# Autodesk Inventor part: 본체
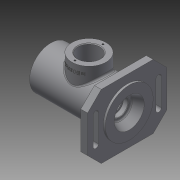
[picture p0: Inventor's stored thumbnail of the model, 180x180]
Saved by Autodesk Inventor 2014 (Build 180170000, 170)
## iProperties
Created: 2017-10
Part Number: 본체
Material: Generic
Document SubType Name: Modeling
Designer: geosung1
Density: 1 g/cm^3
Appearance: Default
Author: geosung1
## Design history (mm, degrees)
sketch "스케치1"
  geometry: L1 (-57.5, 0)-(57.5, 0); L2 (-57.5, 0)-(-57.5, 31); L3 (-57.5, 31)-(54.5, 31); L4 (54.5, 31)-(54.5, 35); L5 (54.5, 35)-(57.5, 35); L6 (57.5, 35)-(57.5, 22); L7 (57.5, 22)-(43.5, 16); L8 (43.5, 16)-(43.5, 12.8); L9 (42.8, 12.5)-(36.2, 12.5); L10 (36.2, 12.5)-(36.2, 10); L11 (36.2, 10)-(33.5, 10); L12 (33.5, 10)-(33.5, 16.5); L13 (33.5, 16.5)-(28.5, 16.5); L14 (28.5, 16.5)-(28.5, 17.5); L15 (28.5, 17.5)-(17.5, 17.5); L16 (17.5, 17.5)-(17.5, 26); L17 (17.5, 26)-(-20.5, 26); L18 (-20.5, 26)-(-20.5, 17.5); L19 (-20.5, 17.5)-(-31.5, 17.5); L20 (-31.5, 17.5)-(-31.5, 18.5); L21 (-31.5, 18.5)-(-33.25, 18.5); L22 (-33.25, 18.5)-(-33.25, 17.5); L23 (-33.25, 17.5)-(-36.5, 17.5); L24 (-36.5, 17.5)-(-36.5, 20); L25 (-36.5, 20)-(-45.5, 20); L26 (-45.5, 20)-(-45.5, 24); L27 (-45.5, 24)-(-48.5, 24); L28 (-48.5, 24)-(-48.5, 0); L29 (42.8, 12.5)-(43.5, 12.904); 2 further points
  constraints: 58 end point, 23 parallel, 3 perpendicular, 2 point on line, 1 coincident, 1 horizontal, 1 midpoint, 1 vertical alignment
  dimensions: "d0" = 115 distance of L1.start L1.end; "d1" = 62 diameter of L2.end L1; "d2" = 70 diameter of L5.end L1; "d3" = 3 distance of L4.end L5.end; "d4" = 44 diameter of L6.end L1; "d5" = 32 diameter of L7.end L1; "d6" = 25 diameter of L9.end L1; "d7" = 20 diameter of L11.end L1; "d8" = 33 diameter of L13.end L1; "d9" = 35 diameter of L15.end L1; "d10" = 52 diameter of L17 L1; "d11" = 35 diameter of L18.end L1; "d12" = 37 diameter of L20.end L1; "d13" = 35 diameter of L23 L1; "d14" = 40 diameter of L25 L1; "d15" = 48 diameter of L27.end L1; "d17" = 9 distance of L28.end L1.start; "d18" = 3 distance of L26.end L27.end; "d19" = 21 horizontal distance of L23.end L1.start; "d20" = 1.75 distance of L20.end L21.end; "d21" = 26 horizontal distance of L1.start L19.end; "d22" = 11 distance of L18.end L19.end; "d23" = 60 horizontal distance of L13.end L19.end; "d24" = 38 distance of L16.end L17.end; "d25" = 5 distance of L12.end L13.end; "d27" = 0.7 horizontal distance of L9.start L8.end; "d28" = 7.3 horizontal distance of L8.end L10.end; "d29" = 14 horizontal distance of L6.end L7.end; "d30" = 30 deg angle of L29 L9; "d31" = 3.2 distance of L7.end L8.end
revolve "회전1" sketch "스케치1" stored, may be unused: angle "d32" = 90 deg
node "작업 평면1"
sketch "스케치2"
  geometry: L1 (-58, 47)-(58, 47); L2 (58, 47)-(58, -47); L3 (58, -47)-(-58, -47); L4 (-58, -47)-(-58, 47); C1 r 31 at (0, 0) reference; 3 further points
  constraints: 8 end point, 2 midpoint, 2 parallel, 1 horizontal, 1 horizontal alignment, 1 perpendicular, 1 vertical alignment
  dimensions: "d34" = 116 distance of L1.start L1.end; "d35" = 94 distance of L1.end L2.end
extrude "돌출1" join sketch "스케치2" distance "d36" = 10; taper "d37" = 0 deg
chamfer "모따기1" distance "d38" = 20; stored, may be unused: second distance "d39" = 2, angle "d40" = 45 deg
sketch "스케치3"
  geometry: L1 (-50, -20)-(-50, 20); L2 (-42, 20)-(-42, -20); C1 r 35 at (0, 0) reference; A1 r 4 centre (-46, 20) between (-42, 20) and (-50, 20); A2 r 4 centre (-46, -20) between (-50, -20) and (-42, -20)
  constraints: 4 end point, 4 point on circle, 4 tangent, 2 centre point, 1 equal radius, 1 vertical alignment
  dimensions: "d41" = 46 horizontal distance of C1.centre A2.centre; "d42" = 8 diameter of A1; "d43" = 40 distance of A1.centre A2.centre; "d44" = 20 vertical distance of C1.centre A2.centre
extrude "돌출2" cut sketch "스케치3" distance "d45" = 10; taper "d46" = 0 deg
hole "구멍1" diameter "d49" = 40.376; stored, may be unused: countersink angle "d53" = 90 deg, drill point angle "d55" = 0 deg; dims "d47" = 10, "d48" = 10, "d50" = 9, "d51" = 4, "d52" = 2, "d54" = 9
node "작업 평면2"
sketch "스케치4"
  geometry: L1 (57.5, 31)-(57.5, -31) reference; C1 r 25 at (1.5, 0); 1 further point
  constraints: 1 centre point, 1 horizontal alignment
  dimensions: "d57" = 50 diameter of C1; "d58" = 56 distance from line of C1.centre L1
extrude "돌출3" join sketch "스케치4" stored distance "d59" = 10; taper "d60" = 0 deg
hole "구멍2" diameter "d63" = 32; stored, may be unused: countersink angle "d67" = 90 deg, drill point angle "d69" = 0 deg; dims "d61" = 10, "d62" = 10, "d64" = 9, "d65" = 4, "d66" = 2, "d68" = 35.9875
sketch "스케치5" dims "d70" = 41
  geometry: L1 (0, 0)-(0, 20.5); C1 r 25 at (0, 0) reference; 1 further point
  constraints: 2 end point, 1 coincident, 1 vertical, 1 vertical alignment, 2 other
hole "구멍3" sketch "스케치5" at (0, 20.5) diameter "d71" = 2.459; stored, may be unused: countersink angle "d75" = 90 deg, drill point angle "d77" = 118 deg; dims "d72" = 6, "d73" = 4, "d74" = 2, "d76" = 8
node "작업 평면3"
sketch "스케치6"
  geometry: L1 (-56, -78)-(-56, -16) reference; L2 (-25, 0)-(25, 0) reference; 2 further points
  constraints: 1 other
  dimensions: "d81" = 56 distance from line of point (0, -10) L1; "d82" = 10 distance from line of L2 point (0, -10)
feature "엠보싱1" sketch "스케치6" dims "d1" = 62, "d83" = 0.5, "d84" = 0
fillet "모깎기1" dims "d85" = 3
chamfer "모따기2" distance "d86" = 1; stored, may be unused: second distance "d87" = 2, angle "d88" = 45 deg
fillet "모깎기2" dims "d89" = 0.3, "d90" = 3
chamfer "모따기3" distance "d91" = 1; stored, may be unused: second distance "d92" = 2, angle "d93" = 45 deg
fillet "모깎기3" dims "d94" = 3
node "솔리드1"
mirror "대칭1"
pattern_circular "원형 패턴1" dims angle "d79" = 360 deg
other parameters: "d33" = -13, "d56" = 47
